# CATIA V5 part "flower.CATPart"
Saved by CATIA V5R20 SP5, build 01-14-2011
Part number: flower
Material "Fire Red": density 7860 kg/m3, Young's modulus 2e+11 Pa, Poisson ratio 0.266
Material "Water": density 1000 kg/m3
Material "Multicoloured Flag"
Bounding box of the stored display mesh (mm): x -45.563 to 45.563, y -45.563 to 61.991, z 0 to 139.66
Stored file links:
  E:\180222112\flower.CATPart
  C:\Program Files\Dassault Systemes\B20\intel_a\startup\materials\Catalog.CATMaterial
  C:\Program Files\Dassault Systemes\B20\intel_a\startup\materials\teak_2.jpg
  C:\Program Files\Dassault Systemes\B20\intel_a\startup\materials\cedar.jpg
  C:\Program Files\Dassault Systemes\B20\intel_a\startup\materials\blue_env_512x512.jpg
  C:\Program Files\Dassault Systemes\B20\intel_a\startup\materials\DS_star.jpg
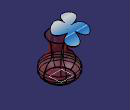
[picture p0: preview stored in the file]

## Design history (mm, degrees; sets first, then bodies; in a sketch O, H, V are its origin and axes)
Body1 (main body), material "Fire Red"
  Plane1: type Offset, RefPlane xy-plane, Offset 20
  Plane2: type Offset, RefPlane Plane1, Offset 20
  Plane3: type Offset, RefPlane Plane2, Offset 20
  Plane4: type Offset, RefPlane Plane3, Offset 20
  Plane5: type Offset, RefPlane Plane4, Offset 20
  Sketch1 on Plane5, origin (0, 0, 100), H (1, 0, 0), V (0, 1, 0)
    circle A1 centre (0, 0) radius 29.8266
  Sketch2 on Plane4, origin (0, 0, 80), H (1, 0, 0), V (0, 1, 0)
    circle A1 centre (0, 0) radius 23.0726
  Sketch3 on Plane3, origin (0, 0, 60), H (1, 0, 0), V (0, 1, 0)
    circle A1 centre (0, 0) radius 21.9749
  Sketch4 on Plane2, origin (0, 0, 40), H (1, 0, 0), V (0, 1, 0)
    circle A1 centre (0, 0) radius 37.8812
  Sketch5 on Plane1, origin (0, 0, 20), H (1, 0, 0), V (0, 1, 0)
    circle A1 centre (0, 0) radius 45.607
  Sketch6 on xy-plane, origin (0, 0, 0), H (1, 0, 0), V (0, 1, 0)
    circle A1 centre (0, 0) radius 31.6229
  Loft1: solid, Sections (Sketch1; Sketch2; Sketch3; Sketch4; Sketch5; Sketch6)
  Shell1: ExtOffset 0, Face face of Loft1, IntOffset 1
Body2, material "Water"
  Sketch7 on yz-plane, origin (0, 0, 0), H (0, 1, 0), V (0, 0, 1)
    axis line L1 (0, 117.0904) -> (0, -14.88)
    point P1 (0, 117.0904)
    line L2 (0, 0) -> (30.5626, 0)
    line L3 (30.5626, 0) -> (41.5502, 9.897)
    line L4 (41.5502, 9.897) -> (44.4279, 15.6349)
    line L5 (44.4279, 15.6349) -> (44.4279, 21.6335)
    line L6 (44.4279, 21.6335) -> (43.1199, 28.9362)
    line L7 (43.1199, 28.9362) -> (0, 28.9362)
    point P8 (0, 28.9362)
    line L8 (0, 28.9362) -> (0, 0)
    coincidence: P1 V, P8 L1
    vertical: L1 V, L5 V, L8 V
    horizontal: L2 H, L7 H
  Shaft1: profile Sketch7, axis Sketch7.L1, angle 360
Body3, material "Multicoloured Flag"
  Sketch8 on yz-plane, origin (0, 0, 0), H (0, 1, 0), V (0, 0, 1)
    spline S1 through (4.925, 3.3767) (15.651, 101.1809) (24.5457, 125.9579)
    point P1 (24.5457, 125.9579)
    point P2 (24.5457, 125.9579)
    coincidence: P1 P2
  Plane6: type Normal, Curve Sketch8, RefPoint vertex of Sketch8
  Sketch9 on Plane6, origin (0, -0.2087, 3.0221), H (-1, 0, 0), V (0, 0.9976, 0.0689)
    circle A1 centre (0, 4.9123) radius 1
    point P1 (0, 4.9123)
    radius A1 = 1
    coincidence: P1 V
  Rib1: profile Sketch9, centre curve Sketch8
  Plane7: type OffsetPt, RefPlane zx-plane, RefPoint Sketch8.P2
  Plane8: type Normal, Curve Sketch8, RefPoint Sketch8.P2
  Sketch10 on Plane8, origin (0, 48.2205, 116.1272), H (1, 0, 0), V (0, -0.9235, 0.3835)
    spline S1 through (-4.3423, 41.7545) (-19.2273, 61.1433) (-37.8855, 41.7545) (-12.0228, 30.6751) (-40.4521, 21.5134) (-23.8706, -3.9187) (-8.5786, 13.9217) (2.1878, -12.1777) (28.996, 6.7624) (7.7842, 19.0587) (34.5873, 27.8468) (18.1132, 54.0973) (-4.3423, 41.7545)
    point P1 (-4.3423, 41.7545)
    point P2 (-4.3423, 41.7545)
    coincidence: P1 P2
  Pad1: profile Sketch10, direction (0, -0.3835, -0.9235), length 1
